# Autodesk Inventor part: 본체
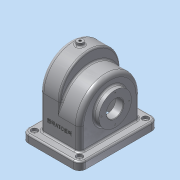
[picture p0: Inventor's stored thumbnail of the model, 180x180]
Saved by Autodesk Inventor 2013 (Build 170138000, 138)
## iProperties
Created: 2017-11
Part Number: 본체
Material: 알루미늄 6061
Document SubType Name: Modeling
Designer: dgall
Density: 2.71 g/cm^3
Mass: 1079.51 g
Surface Area: 1182.07 cm^2
Volume: 398.344 cm^3
Author: dgall
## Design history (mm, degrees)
sketch "스케치1"
  geometry: L1 (58, 0)-(58, -42); L2 (58, -42)-(-58, -42); L3 (-58, -42)-(-58, 0); A1 r 58 centre (0, 0) between (58, 0) and (-58, 0); 2 further points
  constraints: 6 end point, 2 coincident, 2 horizontal alignment, 2 point on circle, 2 tangent, 1 centre point, 1 parallel
  dimensions: "d2" = 116 distance of L1.end L2.end; "d3" = 42 distance of L1.start L1.end; "d4" = 42 distance from line of L2 L1.start
extrude "돌출1" new body sketch "스케치1" distance "d5" = 38; taper "d6" = 0 deg
sketch "스케치3"
  geometry: L1 (-42, -58)-(-42, 58) reference; L2 (23, -58)-(-42, -58); L3 (-42, -58)-(-42, 58); L4 (23, 58)-(-42, 58); A1 r 58 centre (0, 0) between (0, -58) and (0, 58) reference; A2 r 58 centre (23, 0) between (23, -58) and (23, 58)
  constraints: 6 end point, 2 point on circle, 2 tangent, 1 centre point, 1 horizontal alignment
  dimensions: "d9" = 58 radius of A2; "d10" = 65 distance from line of A2.centre L3
extrude "돌출2" join sketch "스케치3" distance "d11" = 38; taper "d12" = 0 deg
feature "쉘1" dims "d13" = 5
sketch "스케치4"
  geometry: L1 (5, 111)-(71, 111) reference; L2 (71, 111)-(71, 5) reference; L3 (71, 5)-(5, 5) reference; L4 (5, 5)-(5, 111) reference; L5 (93, 133)-(93, -17); L6 (93, -17)-(-17, -17); L7 (-17, -17)-(-17, 133); L8 (-17, 133)-(93, 133); 3 further points
  constraints: 8 end point, 2 midpoint, 2 parallel, 1 horizontal, 1 horizontal alignment, 1 perpendicular, 1 vertical alignment
  dimensions: "d14" = 110 distance of L7.end L5.start; "d15" = 150 distance of L5.start L5.end
extrude "돌출3" join sketch "스케치4" distance "d16" = 15; taper "d17" = 0 deg
sketch "스케치5"
  geometry: L1 (-57, -75)-(-57, 75) reference; C1 r 37.5 at (8, 0); 1 further point
  constraints: 1 centre point, 1 horizontal alignment
  dimensions: "d18" = 75 diameter of C1; "d19" = 65 distance from line of C1.centre L1
extrude "돌출4" join sketch "스케치5" distance "d20" = 9; taper "d21" = 0 deg
sketch "스케치6"
  geometry: L1 (57, 75)-(57, -75) reference; C1 r 31 at (-8, 0); A1 r 58 centre (0, 0) between (0, 58) and (0, -58) reference
  constraints: 1 centre point, 1 horizontal alignment
  dimensions: "d22" = 62 diameter of C1; "d23" = 65 distance from line of L1 C1.centre
extrude "돌출5" join sketch "스케치6" distance "d24" = 10; taper "d25" = 0 deg
hole "구멍1" diameter "d28" = 32; stored, may be unused: countersink angle "d32" = 90 deg, drill point angle "d34" = 118 deg; dims "d26" = 10, "d27" = 10, "d29" = 6, "d30" = 4, "d31" = 2, "d33" = 8
node "작업 평면1"
sketch "스케치8"
  geometry: L1 (-76, 116)-(-76, 0) reference; C1 r 6 at (-57, 58); 1 further point
  constraints: 1 centre point, 1 horizontal alignment
  dimensions: "d36" = 12 diameter of C1; "d37" = 19 distance from line of L1 C1.centre
extrude "돌출6" join sketch "스케치8" stored distance "d38" = 10; taper "d39" = 0 deg
hole "구멍2" diameter "d42" = 4.459; stored, may be unused: countersink angle "d46" = 90 deg, drill point angle "d48" = 0 deg; dims "d40" = 10, "d41" = 10, "d43" = 6, "d44" = 4, "d45" = 2, "d47" = 8
sketch "스케치9"
  geometry: C1 r 16 at (0, 0) reference; 2 further points
  constraints: 1 horizontal alignment
  dimensions: "d49" = 26 distance of point (26, 0) C1.centre
hole "구멍3" sketch "스케치9" at (26, 0) diameter "d50" = 2.459; stored, may be unused: countersink angle "d54" = 90 deg, drill point angle "d56" = 118 deg; dims "d51" = 6, "d52" = 4, "d53" = 2, "d55" = 8
sketch "스케치10"
  geometry: C1 r 16 at (0, 0) reference; 2 further points
  constraints: 1 horizontal alignment
  dimensions: "d60" = 29 distance of C1.centre point (29, 0)
hole "구멍4" sketch "스케치10" at (29, 0) diameter "d61" = 2.459; stored, may be unused: countersink angle "d65" = 90 deg, drill point angle "d67" = 118 deg; dims "d62" = 6, "d63" = 4, "d64" = 2, "d66" = 8
fillet "모깎기1" dims "d71" = 12
hole "구멍5" diameter "d74" = 5; stored, may be unused: countersink angle "d78" = 90 deg, drill point angle "d80" = 118 deg; dims "d72" = 10, "d73" = 10, "d75" = 6, "d76" = 12, "d77" = 5, "d79" = 8
hole "구멍6" diameter "d83" = 5; stored, may be unused: countersink angle "d87" = 90 deg, drill point angle "d89" = 118 deg; dims "d81" = 10, "d82" = 10, "d84" = 6, "d85" = 12, "d86" = 5, "d88" = 8
hole "구멍7" diameter "d92" = 5; stored, may be unused: countersink angle "d96" = 90 deg, drill point angle "d98" = 118 deg; dims "d90" = 10, "d91" = 10, "d93" = 6, "d94" = 12, "d95" = 5, "d97" = 8
hole "구멍8" diameter "d101" = 5; stored, may be unused: countersink angle "d105" = 90 deg, drill point angle "d107" = 118 deg; dims "d99" = 10, "d100" = 10, "d102" = 6, "d103" = 12, "d104" = 5, "d106" = 8
chamfer "모따기1" distance "d108" = 1; stored, may be unused: second distance "d109" = 2, angle "d110" = 45 deg
fillet "모깎기2" dims "d111" = 8
fillet "모깎기3" dims "d112" = 3
fillet "모깎기4" dims "d113" = 3
sketch "스케치11"
  geometry: L1 (73, -18)-(-13, -18) reference; L2 (-8, 62)-(-8, 0) reference; 2 further points
  constraints: 1 other
  dimensions: "d114" = 40 distance from line of L1 point (30, 22); "d115" = 38 distance from line of point (30, 22) L2
extrude "돌출7" join sketch "스케치11" distance "d116" = 0.5; taper "d117" = 0 deg
node "솔리드1"
pattern_circular "원형 패턴1" dims angle "d58" = 360 deg
pattern_circular "원형 패턴2" dims angle "d69" = 360 deg
other parameters: "d35" = -144
